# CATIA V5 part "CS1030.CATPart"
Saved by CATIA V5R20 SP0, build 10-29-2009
Part number: CS1030
Revision: 4
Definition: design
Nomenclature: CS1030
Source: made
Description: NOT SPECIFIED
Bounding box of the stored display mesh (mm): x -29 to 29, y -29 to 29, z -55 to 15
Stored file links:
  C:\Users\Raffaele\Desktop\3D X SITO CF\BOLEX\20-TILTED COLUMN SUPPORT\CS1030.CATPart
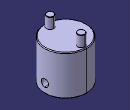
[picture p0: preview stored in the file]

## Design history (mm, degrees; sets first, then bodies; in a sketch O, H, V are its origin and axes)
Body1 "MANIFOLD_SOLID_BREP #715" (main body)
  Solid1: solid without history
